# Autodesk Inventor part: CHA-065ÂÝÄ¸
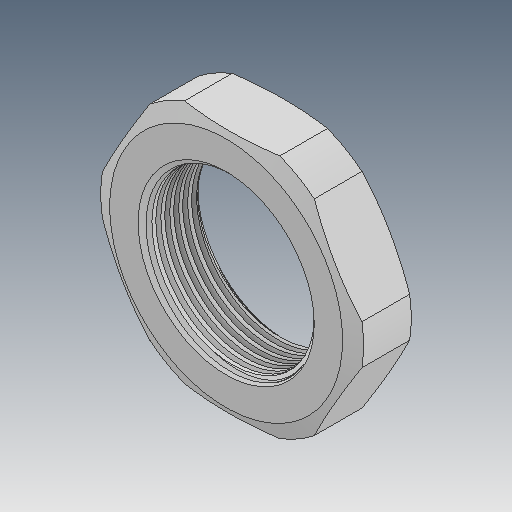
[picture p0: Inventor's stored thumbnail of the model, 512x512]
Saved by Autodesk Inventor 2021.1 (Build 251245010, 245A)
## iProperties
Created: 2019-05
Part Number: CHA-065ÂÝÄ¸
Material: Ogólny
Document SubType Name: Modeling
Designer: user
Density: 1 g/cm^3
Appearance: Domyślna
Author: user
Revision Number: ÈÎºÎ
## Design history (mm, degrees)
feature "¾µÏò1"
node "Bryła1"
